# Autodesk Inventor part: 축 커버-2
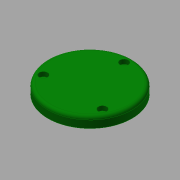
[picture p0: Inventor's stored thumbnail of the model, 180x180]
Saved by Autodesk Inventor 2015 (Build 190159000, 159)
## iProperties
Created: 2015-10
Part Number: 축 커버-2
Document SubType Name: Modeling
Designer: mdu
Density: 7.86 g/cm^3
Material: 강철, 연강
Appearance: 진녹색
Mass: 405.676 g
Surface Area: 133.169 cm^2
Volume: 51.6127 cm^3
Author: mdu
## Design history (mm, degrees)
sketch "스케치1"
  geometry: C1 r 40 at (0, 0) reference; C2 r 26 at (0, 0) reference; 1 further point
  node "참조1"
  node "참조2"
extrude "돌출1" new body sketch "스케치1" distance "d0" = 10; taper "d1" = 0 deg
extrude "돌출2" join sketch "스케치1" distance "d2" = 3; taper "d3" = 0 deg
sketch "스케치2"
  geometry: C1 r 20 at (0, 0); 1 further point
  constraints: 1 centre point, 1 coincident
  dimensions: "d13" = 40 diameter of C1
extrude "돌출3" cut sketch "스케치2" distance "d14" = 3; taper "d15" = 0 deg
sketch "스케치3"
  geometry: C1 r 1.621 at (0, 32.5) reference; 1 further point
hole "구멍2" sketch "스케치3" at (0, 32.5) diameter "d16" = 4.5; stored, may be unused: countersink angle "d20" = 90 deg, drill point angle "d22" = 118 deg; dims "d17" = 6, "d18" = 8, "d19" = 4.4, "d21" = 8
fillet "모깎기1" dims "d26" = 3, "d27" = 0.3
chamfer "모따기1" distance "d28" = 1; stored, may be unused: second distance "d29" = 2, angle "d30" = 45 deg
node "솔리드1"
pattern_circular "원형 패턴1" dims angle "d24" = 360 deg
node "참조3"
